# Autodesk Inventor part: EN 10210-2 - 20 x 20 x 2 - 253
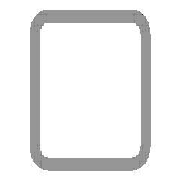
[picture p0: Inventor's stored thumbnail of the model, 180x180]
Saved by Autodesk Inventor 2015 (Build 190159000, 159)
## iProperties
Created: 2015-05
Part Number: EN 10210-2 - 20 x 20 x 2 - 253
Material: Steel, Mild
Description: Tube
Document SubType Name: Modeling
Standard: DIN
Designer: TREINA6
Standard Revision: 1997
Standards Organization: DIN
Language: en-US
Size Designation: 20 x 20 x 2
Categories: <MemberInstance><Categories><Category DisplayName="Structural Shapes" InternalName="089c4875-fa83-4c05-b084-43b9cc11f5ed" Mnemonic="GRDR"><CategoryParameter Dis
Stock Number: 20 x 20 x 2
Density: 7.85 g/cm^3
Appearance: Semi-Polished
IsCustomPart: 1
G_L: 253,000 mm
G_W: 20,000 mm
G_H: 20,000 mm
_CCFamilyMember: 1
_CCFamilyDisplayName: DIN EN 10210-2 (Square) - Tube
_FrameMemberDoc: Frame Member File
_Version: 15.0.0
_GetPNFromCC: 1
Author: TREINA6
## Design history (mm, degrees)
node "Start plane"
node "End plane"
sketch "Sketch"
  geometry: L1 (-10, -7)-(-10, 7); L2 (-7, 10)-(7, 10); L3 (10, 7)-(10, -7); L4 (7, -10)-(-7, -10); L5 (-7, 8)-(7, 8); L6 (8, 7)-(8, -7); L7 (7, -8)-(-7, -8); L8 (-8, -7)-(-8, 7); L9 (0, 14.87)-(0, -14.87) reference; L10 (-14.87, 0)-(14.87, 0) reference; A1 r 3 centre (-7, -7) between (-10, -7) and (-7, -10); A2 r 3 centre (-7, 7) between (-7, 10) and (-10, 7); A3 r 3 centre (7, 7) between (10, 7) and (7, 10); A4 r 3 centre (7, -7) between (7, -10) and (10, -7); A5 r 1 centre (-7, 7) between (-7, 8) and (-8, 7); A6 r 1 centre (7, 7) between (8, 7) and (7, 8); A7 r 1 centre (7, -7) between (7, -8) and (8, -7); A8 r 1 centre (-7, -7) between (-8, -7) and (-7, -8)
  constraints: 16 end point, 16 point on circle, 8 centre point, 8 tangent, 4 parallel, 3 equal radius, 2 perpendicular, 7 other
  dimensions: "d7" = 3 radius of A1 (= G_IR); "d10" = 20 distance between parallel lines of L2 L4 (= G_H); "d11" = 20 distance between parallel lines of L1 L3 (= G_W); "d12" = 2 distance between parallel lines of L3 L6 (= G_T); "d15" = 10 distance between parallel lines of L2 L10 (= 0.5 x d10); "d16" = 10 distance between parallel lines of L9 L3 (= 0.5 x d11)
extrude "Body" new body sketch "Sketch" stored distance "d3" = 253 (= G_L); taper "d4" = 0 deg
node "Driven Length"
  sketch "Sketch3"
    geometry: L1 (0, 0)-(10, 0) reference
    constraints: 2 end point, 1 horizontal
  workplane "Work Plane3"
  sketch "Sketch4"
    geometry: L1 (-2, 0)-(12, 0) reference; L2 (-2, 253)-(12, 253) reference
    dimensions: "d18" = 253 distance between parallel lines of L1 L2 (derived)
body "Solid1"
other parameters: "G_W" = 20 [user parameter; used in 1 equation term], "G_H" = 20 [user parameter; used in 1 equation term], "G_T" = 2 [user parameter; used in 1 equation term], "G_IR" = 3 [user parameter; used in 1 equation term], "G_L" = 253 (= d18) [user parameter; used in 1 equation term], "G_OFFSET_START" = 0 [user parameter; used in 1 equation term], "G_OFFSET_END" = 0 [user parameter; used in 1 equation term], "d13" = 0 (computed from G_OFFSET_START), "d14" = 253 (= G_OFFSET_END + B_L), "B_L" = 253 [user parameter; used in 1 equation term], "d17" = 90 deg
